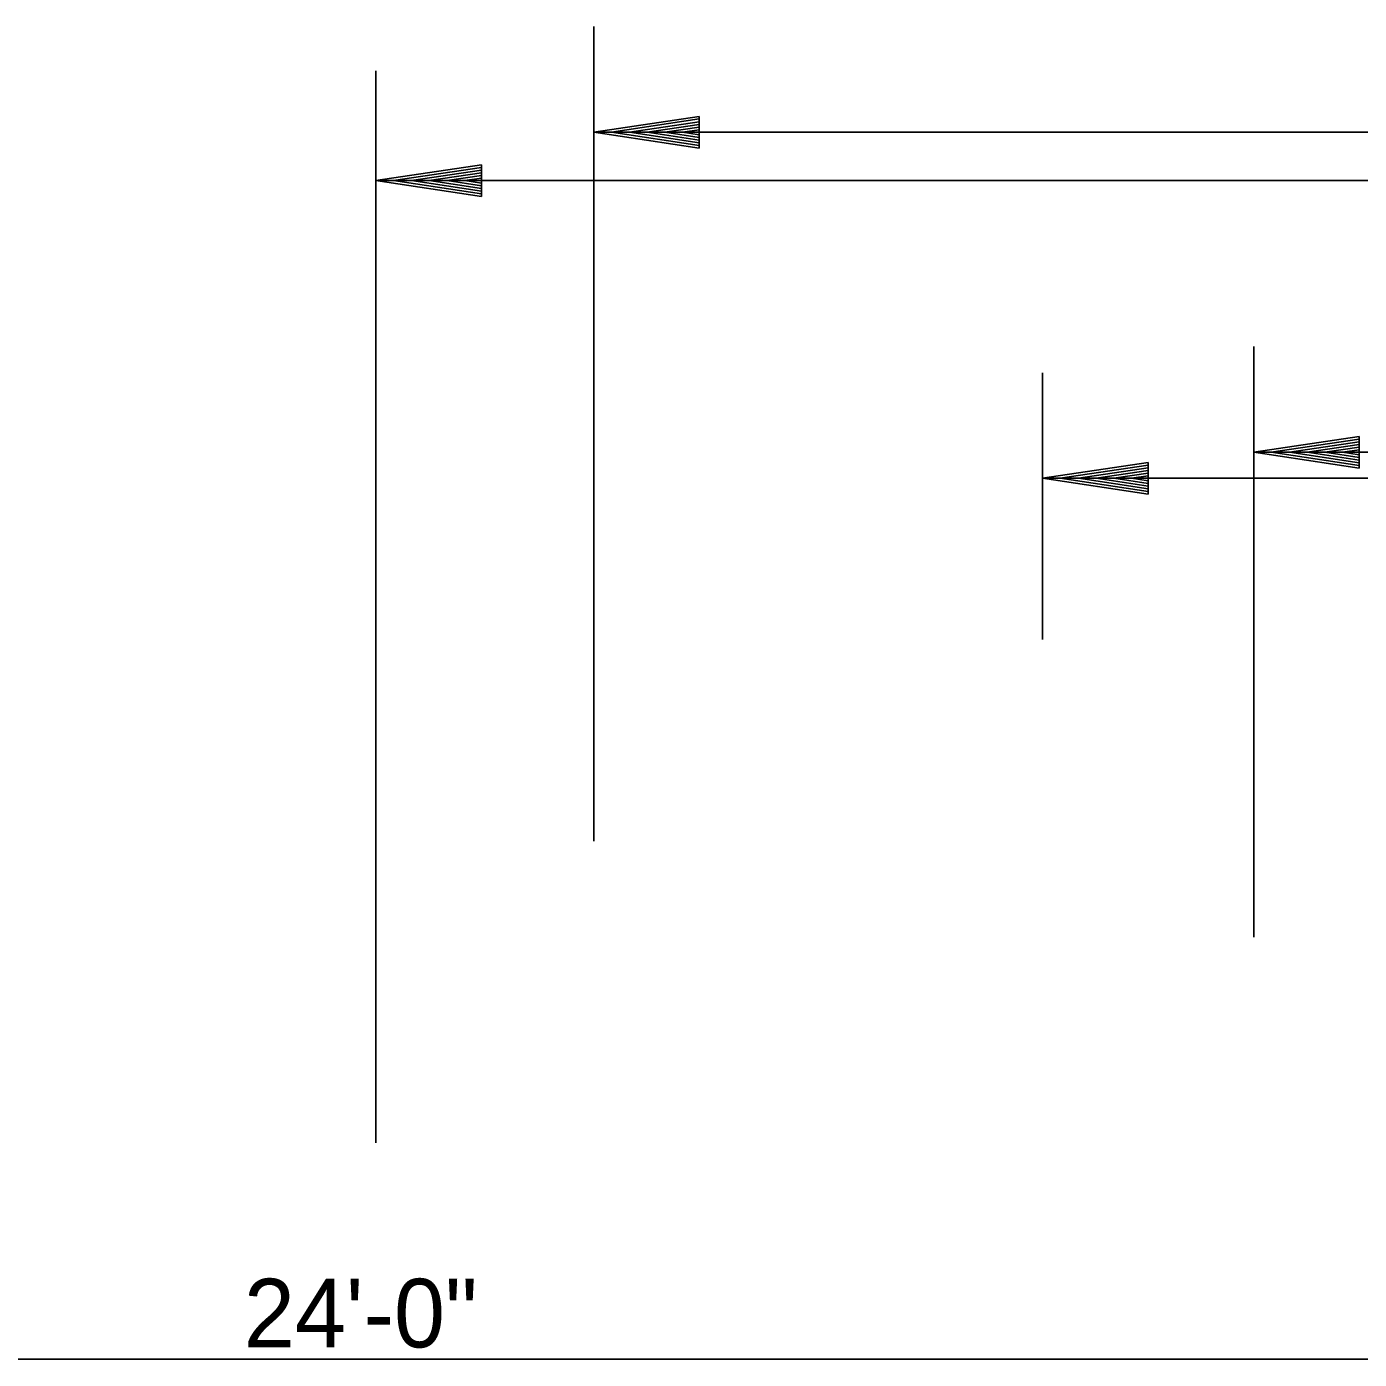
# Model space of a CAD drawing. Extents: x 1373719 to 1374161, y 379835 to 380167.
# Drawn here: x 1373940.09 to 1373952.71, y 380066.13 to 380078.75 of the extents above; entities that cross this region are included whole.
import ezdxf

# ---------------------------------------------------------------- set-up
doc = ezdxf.new("R2010")
doc.units = 0
doc.layers.add('GREEN_TXT', color=7, linetype='Continuous')
doc.layers.add('Text 1', color=7, linetype='Continuous')

msp = doc.modelspace()

# ---------------------------------------------------------------- linework, layer by layer
at = {"layer": 'GREEN_TXT'}
for p, q in [((1373943.398, 380078.332), (1373943.398, 380068.177)), ((1373944.398, 380077.443), (1373943.398, 380077.293)), ((1373944.398, 380077.418), (1373943.565, 380077.293)), ((1373944.398, 380077.143), (1373944.398, 380077.443)), ((1373986.027, 380077.293), (1373943.398, 380077.293)), ((1373944.398, 380077.143), (1373943.398, 380077.293)), ((1373944.398, 380077.168), (1373943.565, 380077.293)), ((1373944.398, 380077.393), (1373943.737, 380077.293)), ((1373944.398, 380077.194), (1373943.737, 380077.293)), ((1373944.398, 380077.368), (1373943.903, 380077.293)), ((1373944.398, 380077.219), (1373943.903, 380077.293)), ((1373944.398, 380077.342), (1373944.073, 380077.293)), ((1373944.398, 380077.245), (1373944.073, 380077.293)), ((1373944.398, 380077.317), (1373944.24, 380077.293)), ((1373944.398, 380077.27), (1373944.24, 380077.293)), ((1373949.714, 380075.473), (1373949.714, 380072.946)), ((1373950.714, 380074.623), (1373949.714, 380074.473)), ((1373950.714, 380074.598), (1373949.881, 380074.473)), ((1373950.714, 380074.572), (1373950.053, 380074.473)), ((1373950.714, 380074.547), (1373950.22, 380074.473)), ((1373950.714, 380074.522), (1373950.389, 380074.473)), ((1373950.714, 380074.323), (1373950.714, 380074.623)), ((1373979.715, 380074.473), (1373949.714, 380074.473)), ((1373950.714, 380074.323), (1373949.714, 380074.473)), ((1373950.714, 380074.348), (1373949.881, 380074.473)), ((1373950.714, 380074.373), (1373950.053, 380074.473)), ((1373950.714, 380074.398), (1373950.22, 380074.473)), ((1373950.714, 380074.424), (1373950.389, 380074.473)), ((1373950.714, 380074.496), (1373950.556, 380074.473)), ((1373950.714, 380074.449), (1373950.556, 380074.473)), ((1373953.714, 380066.126), (1373933.714, 380066.126))]:
    msp.add_line(p, q, dxfattribs=at)
at = {"layer": 'Text 1'}
for p, q in [((1373945.462, 380071.036), (1373945.462, 380078.752)), ((1373946.462, 380077.902), (1373945.462, 380077.752)), ((1373946.462, 380077.877), (1373945.629, 380077.752)), ((1373946.462, 380077.851), (1373945.801, 380077.752)), ((1373946.462, 380077.826), (1373945.968, 380077.752)), ((1373946.462, 380077.801), (1373946.137, 380077.752)), ((1373946.462, 380077.602), (1373946.462, 380077.902)), ((1373945.462, 380077.752), (1373983.962, 380077.752)), ((1373946.462, 380077.602), (1373945.462, 380077.752)), ((1373946.462, 380077.627), (1373945.629, 380077.752)), ((1373946.462, 380077.652), (1373945.801, 380077.752)), ((1373946.462, 380077.677), (1373945.968, 380077.752)), ((1373946.462, 380077.703), (1373946.137, 380077.752)), ((1373946.462, 380077.775), (1373946.304, 380077.752)), ((1373946.462, 380077.728), (1373946.304, 380077.752)), ((1373951.714, 380075.72), (1373951.714, 380070.125)), ((1373952.713, 380074.87), (1373951.713, 380074.72)), ((1373952.713, 380074.845), (1373951.88, 380074.72)), ((1373952.713, 380074.819), (1373952.052, 380074.72)), ((1373952.713, 380074.794), (1373952.219, 380074.72)), ((1373952.713, 380074.769), (1373952.388, 380074.72)), ((1373952.713, 380074.57), (1373952.713, 380074.87)), ((1373952.713, 380074.57), (1373951.713, 380074.72)), ((1373951.714, 380074.72), (1373977.714, 380074.72)), ((1373952.713, 380074.595), (1373951.88, 380074.72)), ((1373952.713, 380074.62), (1373952.052, 380074.72)), ((1373952.713, 380074.645), (1373952.219, 380074.72)), ((1373952.713, 380074.671), (1373952.388, 380074.72)), ((1373952.713, 380074.743), (1373952.555, 380074.72)), ((1373952.713, 380074.696), (1373952.555, 380074.72))]:
    msp.add_line(p, q, dxfattribs=at)

# ---------------------------------------------------------------- texts
at = {"layer": 'GREEN_TXT'}
msp.add_text('24\'-0"', height=0.65, dxfattribs=at).set_placement((1373942.148, 380066.239))

doc.saveas('drawing.dxf')
